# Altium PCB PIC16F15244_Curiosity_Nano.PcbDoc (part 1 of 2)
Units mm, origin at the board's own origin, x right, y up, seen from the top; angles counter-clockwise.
Board outline 50.8 x 20.32 mm, 4 copper layers (Top-Layer, Ground Plane, Power Plane, Bottom Layer), stack 1.59 mm thick; 59 components, 67 nets, 348 pads, 148 vias.
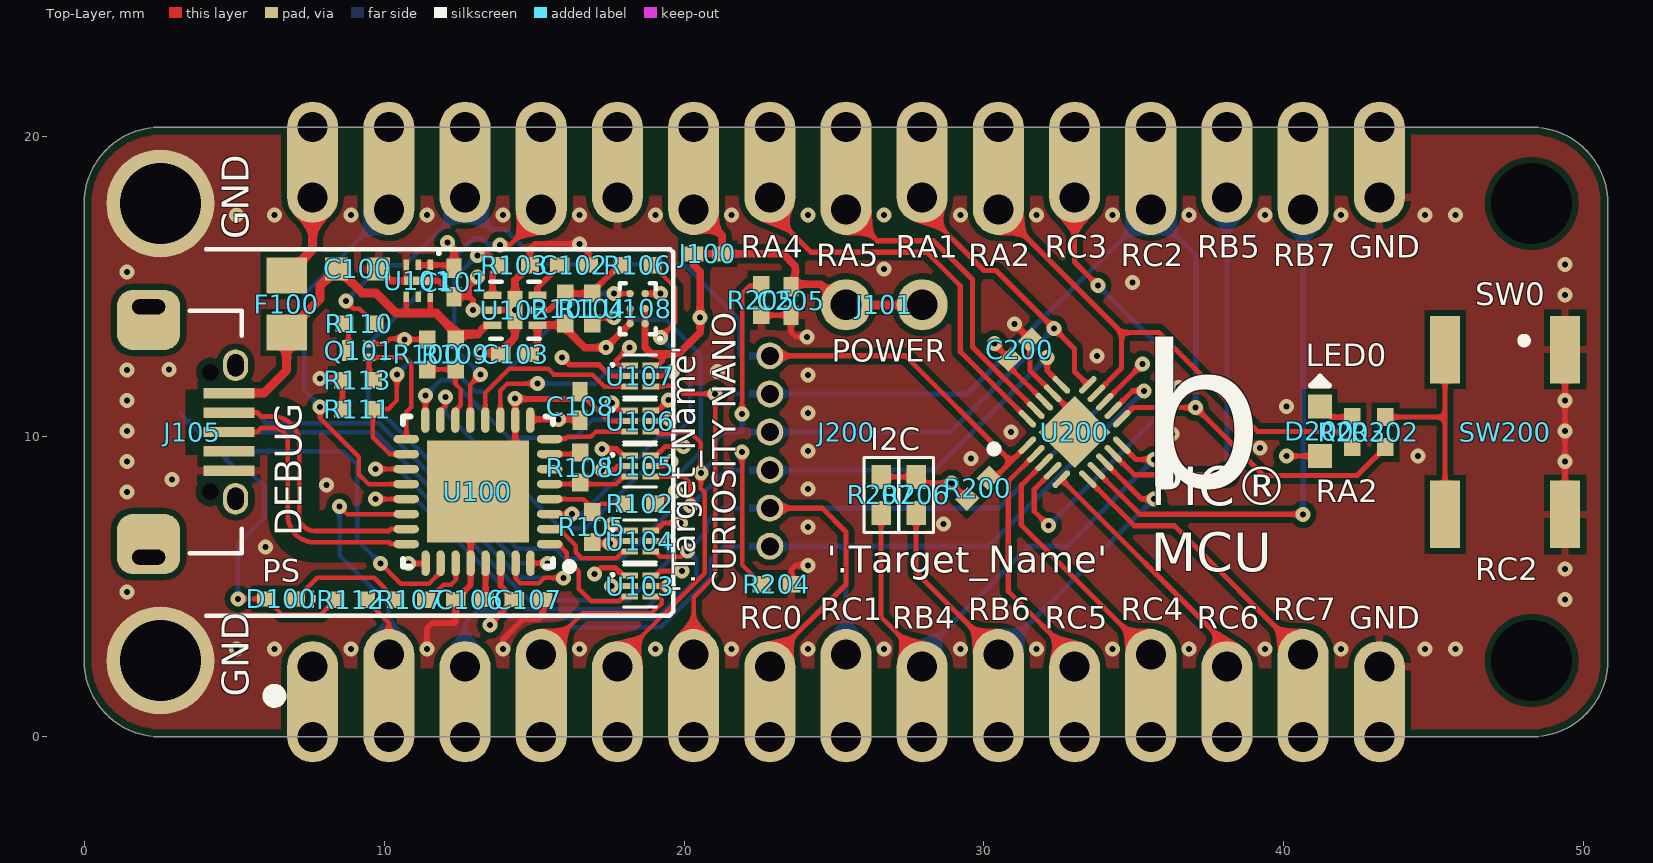
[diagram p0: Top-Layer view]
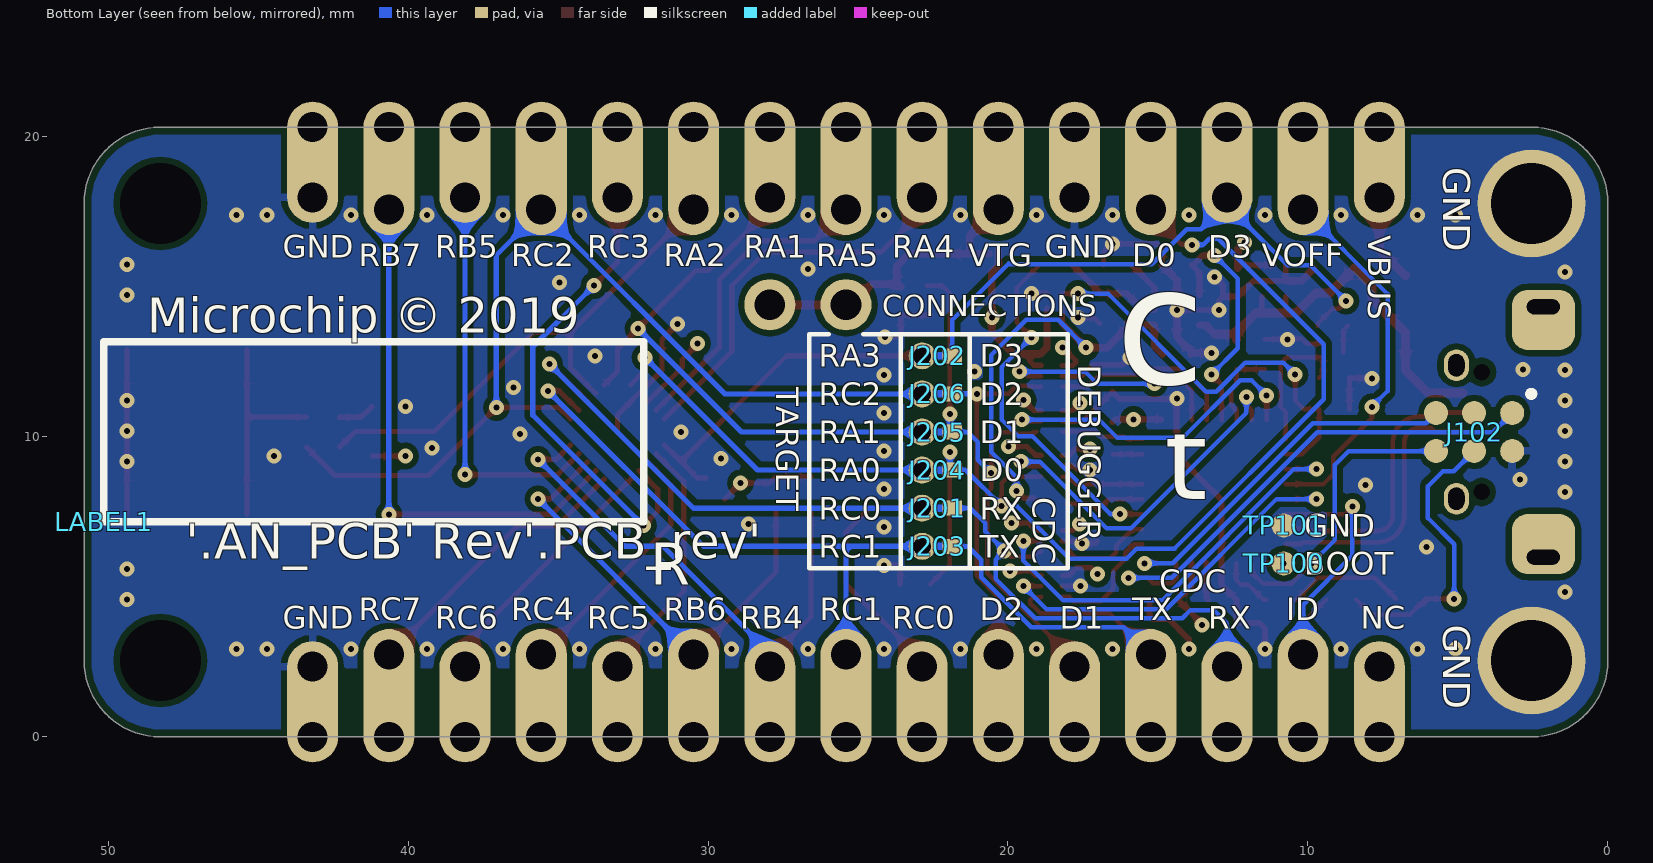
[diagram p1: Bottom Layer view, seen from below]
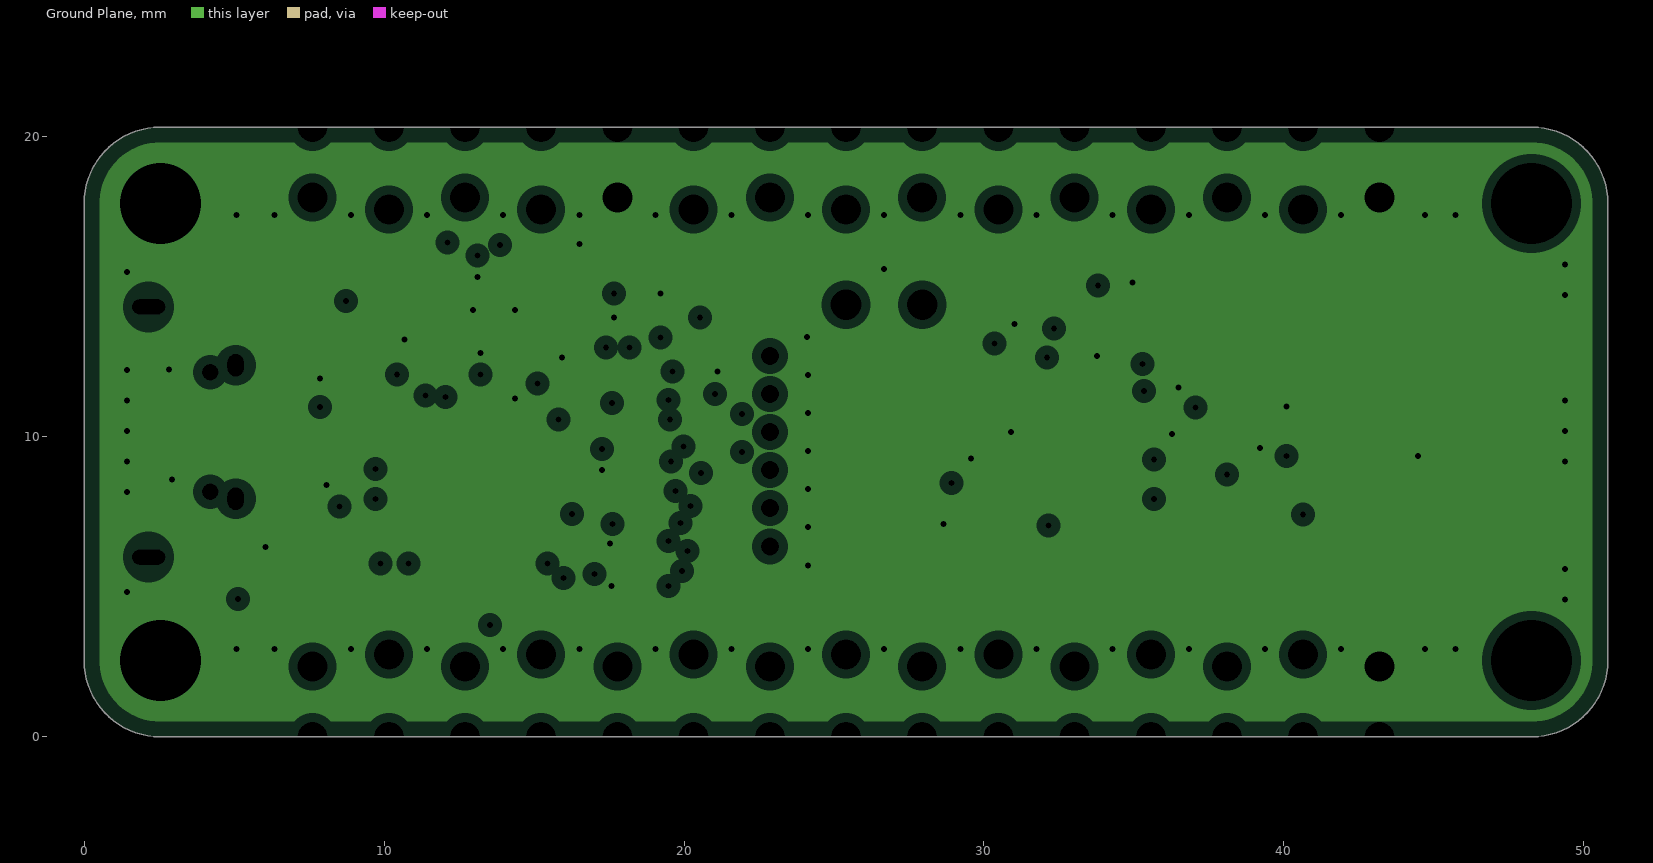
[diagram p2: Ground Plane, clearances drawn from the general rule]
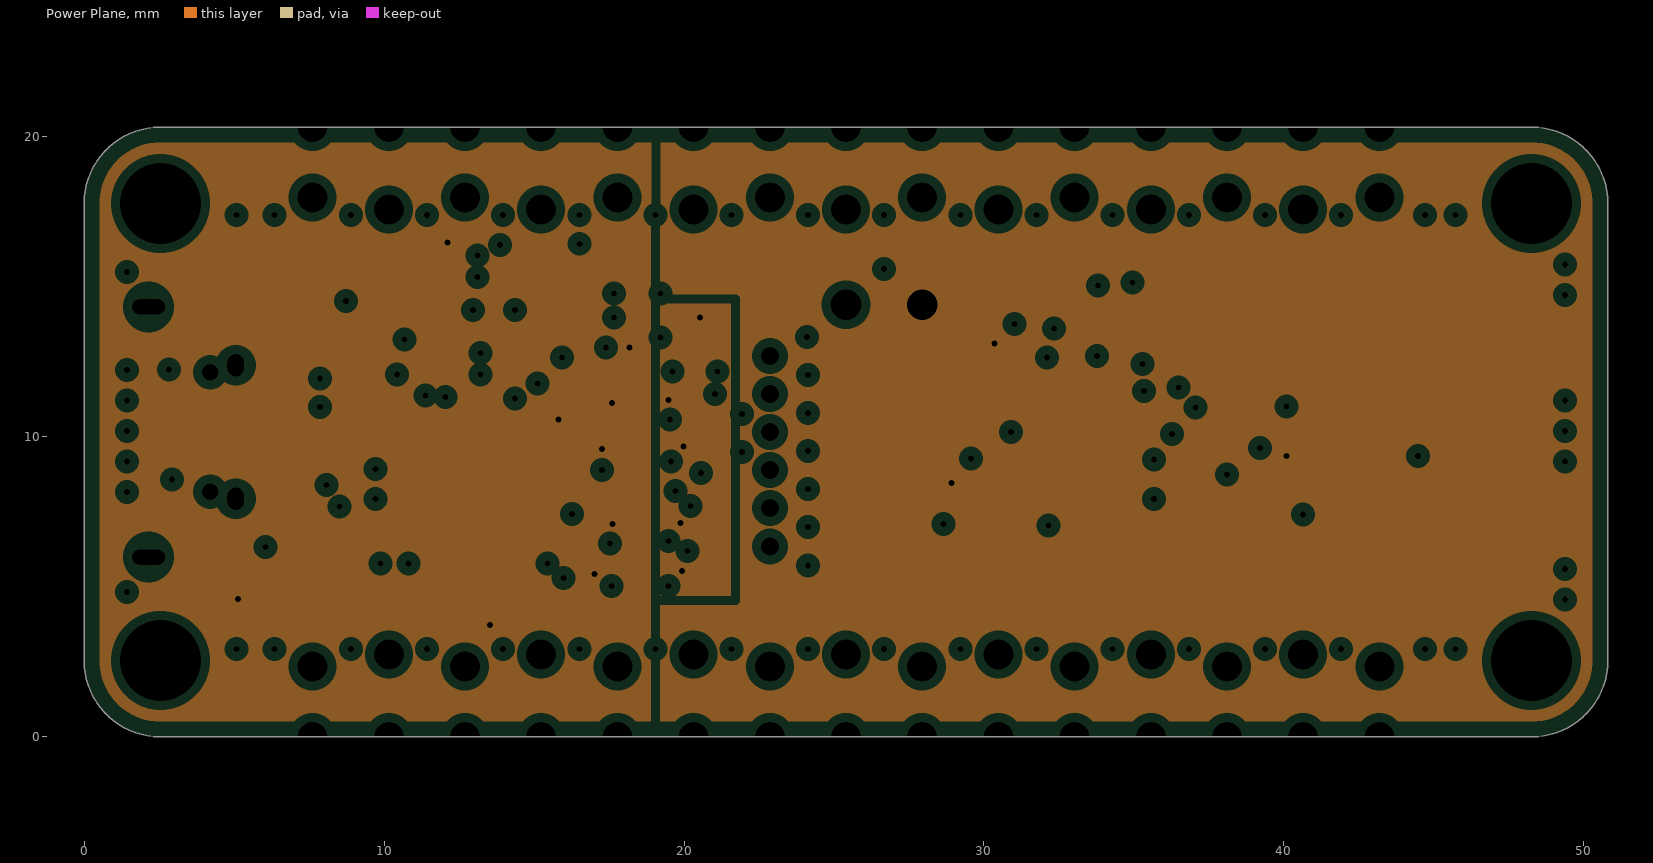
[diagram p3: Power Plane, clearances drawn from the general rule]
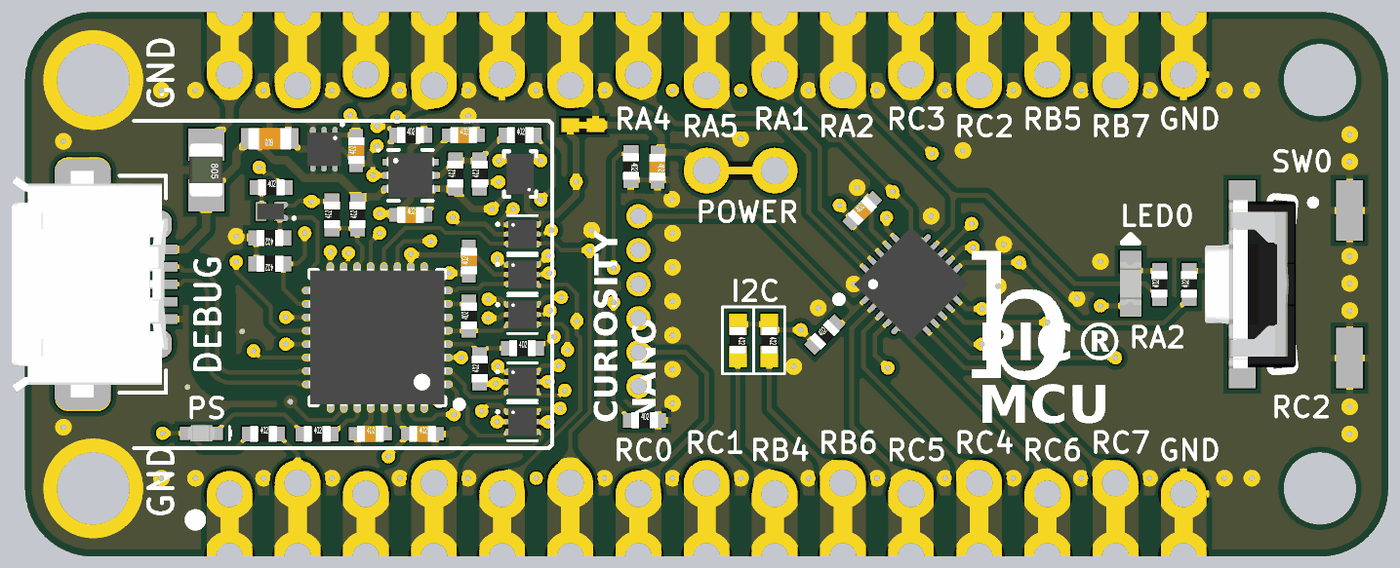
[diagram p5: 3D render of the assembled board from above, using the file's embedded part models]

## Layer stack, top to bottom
Top Solder: solder mask 0.0102, Solder Resist, Dk 3.5
Top-Layer: signal copper 0.035
Dielectric 1: prepreg 0.11, FR-4, Dk 4.2
Ground Plane: plane copper 0.035, net GND
Dielectric 3: core 1.23, Dk 4.2
Power Plane: plane copper 0.035, net (Multiple Nets)
Dielectric 4: prepreg 0.11, Dk 4.2
Bottom Layer: signal copper 0.035
Bottom Solder: solder mask 0.0102, Solder Resist, Dk 3.5

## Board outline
0,2.54 0,17.78 cw(c2.54,17.78) 2.54,20.32 48.26,20.32 cw(c48.26,17.78) 50.8,17.78 50.8,2.54 cw(c48.26,2.54) 48.26,0 2.54,0 cw(c2.54,2.54)

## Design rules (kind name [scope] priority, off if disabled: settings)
AcuteAngle [All] p1: minimum=8.00000000000000E+0001 checktracksonly=TRUE
AssemblyTestPointUsage [All] p1: valid=2 allowmultiple=TRUE
AssemblyTestpoint AssemblyTestpoint_1 [OnBottomLayer and IsComponent] p1: testpointundercomponent=TRUE minsize=0.8 maxsize=2 preferedsize=0.8 minholesize=0 maxholesize=1 preferedholesize=0.25 testpointgrid=0.025 usegrid=FALSE gridtolerance=0 allowsidebottom=TRUE minspacing=1.27 compbodyclearance=1.27
AssemblyTestpoint [All] p2: testpointundercomponent=TRUE minsize=0.8 maxsize=3 preferedsize=0.8 minholesize=0 maxholesize=1 preferedholesize=0.25 testpointgrid=0.025 usegrid=FALSE gridtolerance=0 allowsidebottom=TRUE minspacing=1.27
BoardOutlineClearance BoardOutlineClearance_edge_connector [InComponent('J200') OR InComponent('J201')] p1: gap=0 ignorepadtopadclearanceinfootprint=FALSE
BoardOutlineClearance BoardOutlineClearance_text_top_layer [IsText AND OnTopSilkscreen] p2: gap=0.25 ignorepadtopadclearanceinfootprint=FALSE
BoardOutlineClearance BoardOutlineClearance_FirstPinDot [IsArc AND OnTopSilkscreen] p3: gap=0 ignorepadtopadclearanceinfootprint=FALSE
BoardOutlineClearance [All] p4: gap=0.25 ignorepadtopadclearanceinfootprint=FALSE
Clearance Clearance_Via_in_Pad [IsVia AND (InNet('GND') OR  InNet('BOOT'))] p1: gap=0 ignorepadtopadclearanceinfootprint=FALSE
Clearance Clearance_Poly_Impedance [IsRegion vs InDifferentialPairClass('All Differential Pairs')] p2: gap=0.6 ignorepadtopadclearanceinfootprint=FALSE except(0: Arc-Hole Track-Hole SMDPad-Hole THPad-Hole Via-Hole Fill-Hole Poly-Hole Region-Hole Text-Hole)
Clearance Clearance_Poly [InPoly] p3: gap=0.2 ignorepadtopadclearanceinfootprint=FALSE
Clearance [All] p4: gap=0.15 ignorepadtopadclearanceinfootprint=FALSE
ComponentClearance ComponentClearance_BETWEEN_TESTPOINTS [InComponentClass('Testpoints') vs InComponentClass('Testpoints')] p1: gap=0 collisioncheckmode=3 verticalgap=0 showdistances=FALSE
ComponentClearance ComponentClearance_EDGE [InComponent('J200') or HasFootprint('AP8-01166')] p2: gap=0 collisioncheckmode=3 verticalgap=0 showdistances=FALSE
ComponentClearance ComponentClearance_LABEL [InComponent('LABEL1')] p3: gap=0 collisioncheckmode=3 verticalgap=0 showdistances=FALSE
ComponentClearance [All] p4: gap=0.254 collisioncheckmode=3 verticalgap=0.254 showdistances=TRUE
DiffPairsRouting [All] p1: maxlimit=0.22 minlimit=0.22 mostfreqgap=0.22 toplayer_minwidth=0.16 toplayer_maxwidth=0.16 toplayer_prefwidth=0.16 bottomlayer_minwidth=0.16 bottomlayer_maxwidth=0.16 bottomlayer_prefwidth=0.16 maxuncoupledlength=20
FabricationTestPointUsage TestPointUsage [All] p1: valid=2 allowmultiple=TRUE
FabricationTestpoint Testpoint [All] p1: side=2 testpointundercomponent=TRUE minsize=0.55 maxsize=3 preferedsize=0.8 minholesize=0 maxholesize=1 preferedholesize=0.25 testpointgrid=0 allowsidebottom=TRUE usegrid=FALSE gridtolerance=0 minspacing=1.27
HoleSize [All] p1: absolutevalues=TRUE maxlimit=10 minlimit=0.2 maxpercent=80.000 minpercent=20.000
HoleToHoleClearance HoleToHoleClearance_NPTH [(HoleDiameter > 0) And (PadIsPlated = 'False')] p1: gap=0.25 allowstackedmicrovias=TRUE
HoleToHoleClearance [All] p2: gap=0.3 allowstackedmicrovias=TRUE
MinimumAnnularRing [All] p1: minimumring=0.15
MinimumSolderMaskSliver [All] p1: minsoldermaskwidth=0.08
NetAntennae [Not IsTestpoint] p1: netantennaetolerance=0
PlaneClearance [All] p1: clearance=0.3
PlaneConnect PlaneConnect_VIA [IsVia OR HasPad('Free-666') OR HasPad('Free-EDGE')] p1: planeconnectstyle=Direct reliefexpansion=0.508 reliefentries=4 reliefconductorwidth=0.254 reliefairgap=0.254
PlaneConnect [All] p2: planeconnectstyle=Relief reliefexpansion=0.508 reliefentries=4 reliefconductorwidth=0.254 reliefairgap=0.254
PolygonConnect PolygonConnect_VIA [IsVia OR HasPad('Free-666') OR HasFootprint('AP8-00870')] p1: connectstyle=Direct reliefconductorwidth=0.254 reliefentries=4 polygonreliefangle="90 Angle" airgapwidth=0.254
PolygonConnect [All] p2: connectstyle=Relief reliefconductorwidth=0.254 reliefentries=4 polygonreliefangle="90 Angle" airgapwidth=0.2
RoutingVias [All] p1: holewidth=0.25 width=0.55 viastyle="Through Hole" minholewidth=0.2 minwidth=0.5 maxholewidth=0.5 maxwidth=1
SMDNeckDown [All] p1: percent=98.000
ShortCircuit ShortCircuit_NC_edge_connector [IsPad AND OnLayer('Multi-Layer') AND HasFootprint('AP8-01100') vs IsPad AND OnLayer('Multi-Layer') AND HasFootprint('AP8-01100')] p1: allowed=TRUE
ShortCircuit [All] p2: allowed=FALSE
SilkToSilkClearance SilkToSilkClearance_Text [IsText] p1: silktosilkclearance=0
SilkToSilkClearance [All] p2: silktosilkclearance=0.1
SilkToSolderMaskClearance SilkscreenOverComponentPads_Soldermask [All] p1: minsilkscreentomaskgap=0.12 clearancetoexposedcopper=FALSE
SilkToSolderMaskClearance SilkscreenOverComponentPads_Copper [All] p2: minsilkscreentomaskgap=0.2 clearancetoexposedcopper=TRUE
SolderMaskExpansion SolderMaskTenting [IsVia AND NOT (IsFabTestpoint OR IsAssyTestpoint)] p1: expansion=-1 istentingtop=FALSE
SolderMaskExpansion [All] p2: expansion=0.06 istentingtop=FALSE
ViasUnderSMD ViasUnderSMD_GND [InPadClass('Ground_Pads')] p1: allowed=TRUE
ViasUnderSMD ViasUnderSMD_Testpoint [InNet('BOOT') or InNet('GND')] p2: allowed=TRUE
ViasUnderSMD [All] p3: allowed=FALSE
Width Width_Power [InNetClass('Power')] p1: maxlimit=0.5 minlimit=0.175 preferedwidth=0.25
Width [All] p2: maxlimit=10 minlimit=0.15 preferedwidth=0.15
15 further rules are at their usual default settings.

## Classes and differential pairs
component class S2: C200 C205 D200 J200 J201 J202 J203 J204 J205 J206 R200 R202 R203 R204 R205 R206 R207 SW200 U200
component class S1: C100 C101 C102 C103 C106 C107 C108 D100 F100 J100 J101 J102 J105 Q101 R100 R101 R102 R103 R104 R105 R106 R107 R108 R109 R110 R111 R112 R113 TP100 TP101 U100 U101 U102 U103 U104 U105 U106 U107 U108
component class PIC16F15244_Curiosity_Nano_TopLevel: FW1 LABEL1 PCB1 PCBADOC1 TEST1
differential pair USBD: +USBD_P -USBD_N

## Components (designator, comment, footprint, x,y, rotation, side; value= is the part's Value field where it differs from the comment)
C100 "" AP1-00039 9.118,15.597 r180 top locked value=4.7uF
C101 "Farnell no: 1288200" AP1-00053 12.339,15.15 r90 top locked value=2.2uF
C102 "" AP1-00053 16.34,15.725 r0 top locked value=100n
C103 "" AP1-00053 14.37,12.75 r0 top locked value=2.2uF
C106 "" AP1-00053 12.865,4.575 r0 top locked value=1u
C107 "" AP1-00053 14.815,4.575 r0 top locked value=100n
C108 "" AP1-00053 16.54,11.025 r90 top locked value=100n
C200 "" AP1-00053 31.197,12.909 r45 top value=100n
C205 "" AP1-00053 23.571,14.529 r270 top locked value=2.2uF
D100 "Replacement to A10-0183 / Not proven to be as good at If = 1mA" AP4-00160 6.571,4.6 r180 top locked value="GREEN LED"
D200 "" AP4-00169 41.201,10.181 r270 top locked value="YELLOW LED"
F100 "Farnell no: 1861197" AP2-00002 6.75,14.427 r270 top locked value=MC36213
J100 "" AP8-00595 20.795,16.098 r0 top locked net-tie value="Closed Link"
J101 "" AP8-01183 26.67,14.402 r0 top locked net-tie value="Closed Link 1x2 100mil header"
J102 "" AP8-00997 5.73,10.16 r0 bottom locked value="Testpoint Array"
J105 "" AP8-01099 2.15,10.16 r270 top locked value=MU-MB0142AB2-269
J200 "" AP8-01110 7.62,10.16 r0 top locked value="CNANO30-pin edge connector"
J201 "" AP8-01166 22.335,7.62 r0 bottom locked net-tie value="Closed Link"
J202 "" AP8-01166 22.335,12.7 r0 bottom locked net-tie value="Closed Link"
J203 "" AP8-01166 22.335,6.35 r0 bottom locked net-tie value="Closed Link"
J204 "" AP8-01166 22.335,8.89 r0 bottom locked net-tie value="Closed Link"
J205 "" AP8-01166 22.335,10.16 r0 bottom locked net-tie value="Closed Link"
J206 "" AP8-01166 22.335,11.43 r0 bottom locked net-tie value="Closed Link"
LABEL1 "" AP8-00317 50.14,7.164 r180 bottom value="Label PCBA"
Q101 "" AP5-00056 9.15,12.875 r180 top locked value=DMN65D8LFB
R100 "" AP2-00011 11.439,12.75 r90 top locked value=47k
R101 "" AP2-00011 16.04,14.275 r90 top locked value=47k
R102 "" AP2-00011 18.539,7.775 r0 top locked value=47k
R103 "" AP2-00011 14.365,15.725 r0 top locked value=47k
R104 "" AP2-00011 16.94,14.275 r90 top locked value=27k
R105 "" AP2-00011 16.94,6.999 r90 top locked value=47k
R106 "" AP2-00011 18.452,15.725 r0 top locked value=33k
R107 "" AP2-00011 10.89,4.575 r0 top locked value=1k
R108 "" AP2-00011 16.54,8.974 r90 top locked value=1k
R109 "" AP2-00011 12.389,12.75 r90 top locked value=47k
R110 "" AP2-00011 9.175,13.775 r0 top locked value=1k
R111 "" AP2-00011 9.127,10.922 r180 top value=47k
R112 "" AP2-00011 8.89,4.575 r0 top locked value=1k
R113 "" AP2-00011 9.127,11.887 r180 top value=47k
R200 "" AP2-00011 29.796,8.282 r45 top value=47k
R202 "" AP2-00011 43.385,10.156 r90 top value=1k
R203 "" AP2-00011 42.28,10.156 r90 top value=1k
R204 "" AP2-00011 23.089,5.085 r0 top locked value=47k
R205 "" AP2-00011 22.581,14.554 r270 top locked value=47k
R206 "" AP2-00000 27.737,8.068 r270 top value=4.7k
R207 "" AP2-00000 26.568,8.068 r270 top value=4.7k
SW200 "Rating: DC 12V 50mA / Max 0.1 ohm contact resistance" AP8-00137 47.371,10.16 r270 top locked value=TS604VM1-035CR
TP100 "PCB implemented component." AP8-00870 10.81,5.777 r90 bottom locked value="SMD Test point - 0.8mm"
TP101 "PCB implemented component." AP8-00870 10.81,7.047 r90 bottom locked value="SMD Test point - 0.8mm"
U100 "QFN32" AP6-00418 13.13,8.17 r90 top locked value=SAMD21E18A-MUT
U101 "" AP6-00481 11.139,15.2 r270 top locked value=MIC5528-3.3YMT
U102 "Marking code: AAR" AP6-00504 14.365,14.225 r0 top locked value=MIC5353
U103 "1.05 x 1.05 x 0.4mm" AP6-00505 18.539,5.025 r0 top locked value=74LVC1T45FW4-7
U104 "1.05 x 1.05 x 0.4mm" AP6-00505 18.539,6.525 r0 top locked value=74LVC1T45FW4-7
U105 "1.05 x 1.05 x 0.4mm" AP6-00505 18.539,9.025 r0 top locked value=74LVC1T45FW4-7
U106 "1.05 x 1.05 x 0.4mm" AP6-00505 18.539,10.525 r0 top locked value=74LVC1T45FW4-7
U107 "1.05 x 1.05 x 0.4mm" AP6-00505 18.539,12.025 r0 top locked value=74LVC1T45FW4-7
U108 "" AP6-00513 18.452,14.275 r180 top locked value=MIC94163
U200 "" AP6-00494 33.02,10.16 r45 top value=PIC16F15244-VQFN20

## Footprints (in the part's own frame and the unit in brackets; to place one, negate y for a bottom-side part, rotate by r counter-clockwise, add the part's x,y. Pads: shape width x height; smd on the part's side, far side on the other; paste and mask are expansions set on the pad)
AP1-00039 [mil] "Capacitor 0603 Hight 0.8mm"
  rect 30x30 smd: 1(-27.5,0) 2(27.5,0)
  body extent -31,-16 32,16, height 12
AP1-00053 [mm] "Chip Capacitor, 2-Leads, Body 1.0x0.5mm, IPC High Density"
  rect 0.65x0.5 smd: 1(-0.475,0) 2(0.475,0)
  body extent -0.5,-0.3 0.5,0.3, height 0.2
AP2-00000 [mm] "Standard 0402 SMD resistor footprint"
  rect 0.8x0.65 smd paste-1: 1(-0.6,0) 2(0.6,0)
  silkscreen extent -1.25,-0.58 1.25,0.58, body extent -0.5,-0.3 0.5,0.3, height 0.2
AP2-00002 [mm]
  rect 1.2x1.35 smd: 1(-0.95,0) 2(0.95,0)
  body extent -1,-0.62 1,0.63, height 0.78
AP2-00011 [mm] "Chip Resistor, 2-Leads, Body 1,0x0,5mm, IPC High Density"
  rect 0.6x0.55 smd: 1(-0.5,0) 2(0.5,0)
  body extent -0.5,-0.3 0.5,0.3, height 0.2
AP4-00160 [mm] "ROHM SML-P11 0402 LED"
  rect 0.6x0.5 smd: 1(-0.5,0) 2(0.5,0)
  silkscreen extent -1.14,-0.25 -1.05,0.25, body extent -0.5,-0.3 0.5,0.3, height 0.19
AP4-00169 [mm] "ROHM SML-D1x 0603 LED"
  rect 0.8x0.8 smd: 1(-0.825,0) 2(0.825,0)
  silkscreen extent -1.83,-0.3 -1.53,0.3, body extent -0.8,-0.4 0.8,0.4, height 0.54
AP5-00056 [mm] "DFN1006-3/SOT883, 3-Leads, Body 1,050x0,65mm, Pitch 0,35mm"
  oval 0.508x0.229 on Top Paste: 0(-0.4,0.25) 0(-0.4,-0.25)
  rect 0.4x0.25 smd paste-1: 1(-0.35,0.225) 2(-0.35,-0.225)
  rect 0.4x0.7 smd: 3(0.35,0)
  silkscreen extent -0.92,0.2 -0.83,0.3, body extent -0.5,-0.3 0.5,0.3, height 0.49
AP6-00418 [mm] "MLF-32 solder foot print"
  oval 0.28x0.85 smd paste-0.03 mask+0: 1(-1.746,-2.39) 2(-1.246,-2.39) 3(-0.746,-2.39) 4(-0.246,-2.39) 5(0.254,-2.39) 6(0.754,-2.39) 7(1.254,-2.39) 8(1.754,-2.39) 17(1.754,2.39) 18(1.254,2.39) 19(0.754,2.39) 20(0.254,2.39) 21(-0.246,2.39) 22(-0.746,2.39) 23(-1.246,2.39) 24(-1.746,2.39)
  oval 0.85x0.28 smd paste-0.03 mask+0: 9(2.386,-1.746) 10(2.386,-1.246) 11(2.386,-0.746) 12(2.386,-0.246) 13(2.386,0.254) 14(2.386,0.754) 15(2.386,1.254) 16(2.386,1.754) 25(-2.383,1.746) 26(-2.383,1.246) 27(-2.383,0.746) 28(-2.383,0.246) 29(-2.383,-0.254) 30(-2.383,-0.754) 31(-2.383,-1.254) 32(-2.386,-1.75)
  rect 3.4x3.4 smd paste-1.7 mask+0: 33(0.004,0)
  silkscreen extent -2.62,-3.18 2.5,2.5, body extent -2.55,-2.55 2.55,2.55, height 1
AP6-00481 [mm] "6 Pin 1.2mm X 1.2mm Thin DFN"
  oval 0.483x0.203 on Top Paste: 0(-0.597,0.412) 0(-0.597,0) 0(-0.597,-0.412) 0(0.597,0.412) 0(0.597,0) 0(0.597,-0.412)
  rect 0.35x0.18 smd paste-0.09 mask+0.05: 1(-0.531,0.4) 2(-0.531,0) 3(-0.531,-0.4) 4(0.531,-0.4) 5(0.531,0) 6(0.531,0.4)
  rect 0.28x0.94 smd paste-0.02 mask+0.05: 7(0,0)
  silkscreen extent -0.97,0.64 -0.88,0.74, body extent -0.63,-0.62 0.63,0.63, height 0.6
AP6-00494 [mm] "20-pad, 3 x 3 x 0.85 mm body, lead pin pitch 0.4mm. Plastic Very Thin Quad Flat No Lead Package (VQFN) Sawn"
  oval 0.75x0.2 smd mask+0.06: 1(-1.425,0.8) 2(-1.425,0.4) 3(-1.425,0) 4(-1.425,-0.4) 5(-1.425,-0.8) 11(1.425,-0.8) 12(1.425,-0.4) 13(1.425,0) 14(1.425,0.4) 15(1.425,0.8)
  oval 0.2x0.75 smd mask+0.06: 6(-0.8,-1.425) 7(-0.4,-1.425) 8(0,-1.425) 9(0.4,-1.425) 10(0.8,-1.425) 16(0.8,1.425) 17(0.4,1.425) 18(0,1.425) 19(-0.4,1.425) 20(-0.8,1.425)
  rect 1.7x1.7 smd paste-2 mask+0.06: 21(0,0)
  silkscreen extent -2.42,1.38 -2.18,1.62, body extent -1.5,-1.5 1.5,1.5, height 0.9
AP6-00504 [mm] "MLF, 6-Leads, Body 1,60x1,60mm, Pitch 0,50mm, Thermal Pad 1,26x0,33mm, IPC High Density"
  rect 0.6x0.25 smd mask+0.05: 1(-0.75,0.5) 2(-0.75,0) 3(-0.75,-0.5) 4(0.75,-0.5) 5(0.75,0) 6(0.75,0.5)
  rect 0.5x1.26 smd paste-0.1 mask+0.05: 7(0,0)
  silkscreen extent -1.25,-0.95 0.82,1, body extent -0.87,-0.82 0.87,0.82, height 0.55
AP6-00505 [mm] "X2-DFN1010, 6-Leads, Body 1,05x1,05mm, Pitch 0,35mm, IPC High Density"
  oval 0.559x0.178 on Top Paste: 0(-0.375,-0.401) 0(-0.375,0) 0(-0.375,0.401) 0(0.375,-0.401) 0(0.375,0) 0(0.375,0.401)
  rect 0.55x0.2 smd paste-0.1: 1(-0.35,0.35) 2(-0.35,0) 3(-0.35,-0.35) 4(0.35,-0.35) 5(0.35,0) 6(0.35,0.35)
  silkscreen extent -0.97,-0.7 0.55,0.7, body extent -0.53,-0.53 0.53,0.53, height 0.4
AP6-00513 [mm] "BGA, 6-Leads, Body 1,00x1,50mmx0,80mm, Pitch 0,50mm"
  round 0.25 smd mask+0.05: A1(-0.25,0.5) A2(0.25,0.5) B1(-0.25,0) B2(0.25,0) C1(-0.25,-0.5) C2(0.25,-0.5)
  silkscreen extent -0.8,-0.85 0.6,1.05, body extent -0.5,-0.75 0.5,0.75, height 0.8
AP8-00137 [mm]
  rect 2.25x1 smd: 1(-2.75,2) 2(2.75,2) 3(-2.75,-2) 4(2.75,-2)
  silkscreen extent -3.15,0.54 -2.95,0.73, body extent -3.4,-3.21 3.4,3.22, height 3.47
AP8-00317 [mm] "Placement area for 18x6mm sticker"
  silkscreen extent 0,0 18,6
AP8-00595 [mm]
  rect 0.65x0.5 smd paste-1: 1(-0.475,0) 2(0.475,0)
  Top-Layer lines w0.254: -0.175,0 0.2,0
AP8-00870 [mil] "TP_SMT_.8mm"
  round 31.5 smd paste-39.37: 1(0,0)
AP8-00997 [mm] "SMT test point array 2x5 0.8mm, Pitch 1.27 mm"
  round 0.8 smd paste-1: 1(-2.54,-0.635) 2(-2.54,0.635) 3(-1.27,-0.635) 4(-1.27,0.635) 5(0,-0.635) 6(0,0.635)
  silkscreen extent -3.28,-1.37 -3.07,-1.17
AP8-01099 [mm] "Micro USB AB connector from Allen Creations. Signals surface mount, shield DIP"
  rrect52% 2x2.1 on Top Paste: 0(-3.69,0) 0(3.69,0)
  rrect100% 1.05x0.84 on Top Paste: 0(-2.225,2.9) 0(2.225,2.9)
  rect 0.35x1.7 smd: 1(-1.3,2.68) 2(-0.65,2.68) 3(0,2.68) 4(0.65,2.68) 5(1.3,2.68)
  rrect52% 2x2.1 hole 0.5 slot 1.1 at 90 deg copper offset 0.437,0: 6(-4.175,0)
  rrect52% 2x2.1 hole 0.5 slot 1.1 at 90 deg copper offset -0.437,0: 7(4.175,0)
  rrect100% 1.05x0.84 hole 0.54 slot 0.75 at 0 deg: 8(-2.225,2.9) 9(2.225,2.9)
  round 0 hole 0.55 unplated: 10(-2,2.05) 11(2,2.05)
  silkscreen extent -4.05,1.38 4.05,3.1, body extent -4.32,-2.65 4.33,3.25, height 2.78
AP8-01110 [mil] "30-pin Header staggered with castellations (for CNANO)"
  round 75 on Top Solder: 0(0,-400) 0(0,400) 0(100,-400) 0(100,400) 0(200,-400) 0(200,400) 0(300,-400) 0(300,400) 0(400,-400) 0(400,400) 0(500,-400) 0(500,400) 0(600,-400) 0(600,400) 0(700,-400) 0(700,400) 0(800,-400) 0(800,400) 0(900,-400) 0(900,400) 0(1000,-400) 0(1000,400) 0(1100,-400) 0(1100,400) 0(1200,-400) 0(1200,400) 0(1300,-400) 0(1300,400) 0(1400,-400) 0(1400,400)
  oval 67x155 hole 39.37 copper offset 0,44 mask-20: 1(0,-400) 3(200,-400) 5(400,-400) 7(600,-400) 9(800,-400) 11(1000,-400) 13(1200,-400) 15(1400,-400)
  round 67 hole 39.37 mask+3.94: 1(0,-308) 2(100,-292) 3(200,-308) 4(300,-292) 5(400,-308) 6(500,-292) 7(600,-308) 8(700,-292) 9(800,-308) 10(900,-292) 11(1000,-308) 12(1100,-292) 13(1200,-308) 14(1300,-292) 15(1400,-308) 16(1400,308) 17(1300,292) 18(1200,308) 19(1100,292) 20(1000,308) 21(900,292) 22(800,308) 23(700,292) 24(600,308) 25(500,292) 26(400,308) 27(300,292) 28(200,308) 29(100,292) 30(0,308)
  oval 67x171 hole 39.37 copper offset 0,52 mask-20: 2(100,-400) 4(300,-400) 6(500,-400) 8(700,-400) 10(900,-400) 12(1100,-400) 14(1300,-400)
  oval 67x155 hole 39.37 copper offset 0,-44 mask-20: 16(1400,400) 18(1200,400) 20(1000,400) 22(800,400) 24(600,400) 26(400,400) 28(200,400) 30(0,400)
  oval 67x171 hole 39.37 copper offset 0,-52 mask-20: 17(1300,400) 19(1100,400) 21(900,400) 23(700,400) 25(500,400) 27(300,400) 29(100,400)
  Multi-Layer pour cut-out: 1434,310 1434,450 -34,450 -34,310
  Multi-Layer pour cut-out: -34,-310 -34,-450 1434,-450 1434,-310
AP8-01166 [mm] "Cut-Strap 0402 with hole"
  rect 0.65x0.5 smd paste-1: 1(-0.475,0)
  round 0.9 hole 0.6 paste-1: 2(0.525,0)
  Top-Layer region: -0.175,0.125 0.175,0.125 0.175,-0.125 -0.175,-0.125
AP8-01183 [mm] "closed link, 100-mil 1 x 2 pin header footprint"
  round 1.7 hole 1.02: 1(-1.27,0) 2(1.27,0)
  Top-Layer lines w0.3: -1.27,0 1.27,0

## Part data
C100: library part A01-0377, "Ceramic capacitor, SMD 0603, X5R, 10V, 10% (de31036)", Manufacturer="WALSIN Technology Corporation", MPN=0603X475K100CT, TemperatureRange="-55 - +85 deg C", Tolerance=10%
C101: library part A01-0300, "Ceramic capacitor, SMD 0402, X5R, 6.3V, +/-20%", Manufacturer=Kemet, MPN=C0402C225M9PAC, TemperatureRange="-55Â°C to +85Â°C", Tolerance=Â±20%
C102 C107 C108 C200: library part A01-0246, "Ceramic capacitor, SMD 0402, X7R, 16V, +/-10%", Manufacturer=Kemet, MPN=C0402C104K4RACTU, TemperatureRange="-55 - +125 deg C", Tolerance="16V, +/-10%"
C103 C205: library part A01-0493, "CAP CER 2.2UF 10V 10% X5R 0402", Manufacturer=tdk, MPN=C1005X5R1A225K, TemperatureRange="-55 to 85C", Tolerance=+/-10%
C106: library part A01-0286, "Ceramic capacitor, SMD 0402, X5R, 6.3V, +/-10% (de26942)", Manufacturer=Kemet, MPN=C0402C105K9PAC, TemperatureRange="-55 to 85 deg C", Tolerance=+/-10%
D100: library part A10-0213, "LED, SMD 0402, Green, Wave length=569nm, 2.1mcd @ (1mA, 1.9Vf)rohm", Manufacturer=ROHM, MPN=SML-P12MTT86R, TemperatureRange="-40 to +85"
D200: library part A10-0218, "LED, SMD 0603, Yellow, Wave length=590nm, 100mcd @ (20mA, 2.2Vf) rohm", Manufacturer=ROHM, MPN=SML-D12Y1WT86, TemperatureRange="-40 to +85"
F100: library part A02-0622, "Resetable PTC fuse, Ih = 0.5A, It = 1.0A, 0805 package", Manufacturer=Multicomp, MPN=MC36213, TemperatureRange="-40°C to + 85°C"
J100: library part A08-1454, "Closed Link 0402"
J101: library part A08-3029, "Closed Link with w/hole for 1x2 100mil header"
J102: library part A08-2568, "10-pin Testpoint Array, 0.8mm Pad, 1.27mm Pitch"
J105: library part A08-2839, "USB micro AB, Surface mount signals and DIP shield", Manufacturer="Allen Creations Corp.", MPN=MU-MB0142AB2-269, TemperatureRange="-30Â°C to +80Â°C"
J200: library part A08-2846, "Curiosity Nano 30-pin edge connector with castellations, 100-mil pitch."
J201 J202 J203 J204 J205 J206: library part A08-2981, "Closed Link 0402 w/50mil hole"
LABEL1: library part A09-0611, "PCBA identification label PP Top White Gloss", Manufacturer="ACT Logimark AS", MPN=505462
Q101: library part A05-0180, "N-channel MOSFET, DFN1006-3 (SOT883), 60V, 330mA, 4Ohm", Manufacturer="Diodes Incorporated", MPN=DMN65D8LFB-7, TemperatureRange="-55Â°C to +150Â°C"
R100 R101 R102 R103 R105 R109 R111 R113 R200 R204 R205: library part A02-0252, "Thick film resistor, SMD 0402, 1/16W, 1%", Manufacturer=KOA, MPN=RK73H1ETTP4702F, TemperatureRange="-55 - +125 deg C", Tolerance="1 %"
R104: library part A02-0246, "Thick film resistor, SMD 0402, 1/16W, 1%", Manufacturer=Yageo, MPN=RC0402FR-0727KL, TemperatureRange="-55 - +125 deg C", Tolerance="1 %"
R106: library part A02-0248, "Thick film resistor, SMD 0402, 1/16W, 1%", Manufacturer="ASJ Holdings", MPN=CR10-3302-FK, TemperatureRange="-55 - +125 deg C", Tolerance="1 %"
R107 R108 R110 R112 R202 R203: library part A02-0212, "Thick film resistor, SMD 0402, 1/16W, 1%", Manufacturer="ASJ Holdings", MPN=CR10-1001-FK, TemperatureRange="-55 - +125 deg C", Tolerance="1 %"
R206 R207: library part A02-1016, "Thick film resistror, SMD 0402, 1/16W, 1%", Manufacturer=Yageo, MPN=RC0402FR-074K7L, TemperatureRange="-55 to +155 deg C", Tolerance=1%
SW200: library part A08-2830, "SWITCH, SMD, 260gf, 6.4mm X 6.2mm", Manufacturer="Dailywell Electronics Co.LTD", MPN=TS604VM1-035CR-R, TemperatureRange="-40 - +85 deg C"
TP100 TP101: library part A08-2176, "SMD Test point - 0.8mm"
U100: library part A06-1205, "32-bit RISC MCU 32pin", Manufacturer=Microchip, MPN=ATSAMD21E18A-MUT, TemperatureRange="-40Â°C to +85Â°C"
U101: library part A06-1475, "LDO 3.3V 0.5A 6TDFN", Manufacturer=Microchip, MPN=MIC5528-3.3YMT-T5, TemperatureRange="-40Â°C ~ 125Â°C"
U102: library part A06-1578, "500mA Ultra Low Dropout LDO regulator, 2% accuracy, 1.6x1.6mm MLF", Manufacturer=Microchip, MPN=MIC5353YMT-TR, TemperatureRange="-40Â°C to +125Â°C"
U103 U104 U105 U106 U107: library part A06-1580, "Single-Bit Dual-Supply Transceive, 1.65-5.5 Translation and 3-State Outputs", Manufacturer="Diodes Incorporated", MPN=74LVC1T45FW4-7, TemperatureRange="-40C - 125C"
U108: library part A06-1613, "Loadswitch, Rds(on) = 14.5mohm, 1.0mm x 1.5mm WLCSP, reverse blocking", Manufacturer=Microchip, MPN=MIC94163YCS-TR, TemperatureRange="-40Â°C to +125Â°C"
U200: library part A06-1719, "PIC 8-bit RISC MCU, VQFN-20, 3mm x 3mm", Manufacturer=Microchip, MPN=PIC16F15244-I/REB, TemperatureRange="-40°C to 85°C"

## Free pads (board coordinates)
  round 0 hole 2.7 unplated paste-2.6: 0(48.26,2.54) 0(48.26,17.78)
  round 3.6 hole 2.7 paste-2.6: 666(2.54,2.54) 666(2.54,17.78)

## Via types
v1: diameter 0.5, hole 0.2, Top-Layer to Bottom Layer, 144 vias
v2: diameter 0.5, hole 0.2, Top-Layer to Bottom Layer, tented both sides, 2 vias
v3: diameter 0.5, hole 0.2, Top-Layer to Bottom Layer, tented top, 2 vias

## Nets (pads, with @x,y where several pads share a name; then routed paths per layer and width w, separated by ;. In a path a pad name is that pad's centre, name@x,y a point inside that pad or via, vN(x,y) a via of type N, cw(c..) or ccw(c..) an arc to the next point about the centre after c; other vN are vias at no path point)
BOOT: TP100.1 U100.25 | length 0.6
  Top-Layer w0.2: v3(10.81,5.777) U100.25@11.393,5.777
CDC_RX: J200.3 J201.1 U104.4 | length 14.8
  Top-Layer w0.15: U104.4@18.889,6.175 19.031,6.175 19.206,6 19.915,6 v1(20.115,6.2)
  Bottom Layer w0.15: J200.3@12.7,2.54 12.7,3.785 13.14,4.225 13.915,4.225 14.19,3.95 19.096,3.95 20.415,5.269 20.415,5.9 v1(20.115,6.2) 20.752,6.837 20.752,7.117 21.255,7.62 J201.1@21.86,7.62 ; J201.1@21.86,7.61 J201.1@21.91,7.61
CDC_RX_CTRL: U100.19 U104.5 | length 14.4
  Top-Layer w0.15: v1(9.715,8.925) U100.19@10.74,8.924 ; U104.5@18.889,6.525 v1(19.49,6.525)
  Bottom Layer w0.15: v1(9.715,8.925) 10.47,8.925 14.845,4.55 18.165,4.55 19.49,5.875 v1(19.49,6.525)
CDC_TX: J200.4 J203.1 U103.4 | length 13.7
  Top-Layer w0.15: J200.4@15.24,2.743 16.622,4.125 18.925,4.125 19.15,4.35 19.165,4.35 19.253,4.438 19.253,4.562 19.165,4.65 18.914,4.65 U103.4@18.889,4.675
  Bottom Layer w0.15: J200.4@15.24,2.743 16.147,3.65 19.22,3.65 20.89,5.32 20.89,5.9 21.34,6.35 J203.1@21.86,6.35
CDC_TX_CTRL: U100.21 U103.5 | length 13.2
  Top-Layer w0.15: v1(9.715,7.924) U100.21@10.74,7.924 ; U103.5@18.889,5.025 v1(19.49,5.025)
  Bottom Layer w0.15: v1@9.715,7.925 11.046,7.925 14.721,4.25 18.715,4.25 v1(19.49,5.025)
DAC: R106.2 U100.3 | length 12.1
  Top-Layer w0.15: U100.3@15.52,7.424 v1(16.264,7.424) ; R106.2@18.952,15.725 19.714,14.963 19.714,13.816 v1(19.215,13.317) v1@19.215,13.267
  Bottom Layer w0.15: v1(16.264,7.424) 16.589,7.424 19.189,10.024 19.664,10.024 20.215,10.575 20.215,12.317 v1(19.215,13.317)
DBG0: J200.27 J204.1 R204.1 U105.4 | length 33
  Top-Layer w0.15: v1(13.865,16.4) 13.881,16.416 14.221,16.416 15.24,17.435 J200.27@15.24,17.577 ; U105.4@18.889,8.675 19.987,8.675 20.215,8.447 v1(20.215,7.7) ; v1(21.935,9.485) 21.935,5.739 R204.1@22.589,5.085
  Bottom Layer w0.15: v1(13.865,16.4) 13.49,16.4 13.29,16.6 12.987,16.6 9.473,13.086 9.473,11.248 14.446,6.275 15.71,6.275 16.044,5.941 17.956,5.941 19.715,7.7 v1(20.215,7.7) 21.405,8.89 J204.1@21.86,8.89 ; J204.1@21.935,8.89 v1(21.935,9.485)
DBG0_CTRL: U100.15 U105.5 | length 12.1
  Top-Layer w0.15: U100.15@11.876,10.556 11.876,10.861 12.051,11.036 v1(12.051,11.325) ; U105.5@18.889,9.025 19.332,9.025 19.482,9.175 v1(19.564,9.175)
  Bottom Layer w0.15: v1(12.051,11.325) 12.051,10.796 15.903,6.944 16.713,6.944 18.943,9.175 v1(19.564,9.175)
DBG1: J200.5 J205.1 R205.1 U106.4 | length 17.9
  Top-Layer w0.15: J200.5@17.78,2.54 20.69,5.45 20.69,8.15 20.565,8.275 v1(20.565,8.79) 20.565,9.794 20.209,10.15 19.786,10.15 19.736,10.1 19.14,10.1 U106.4@19.065,10.175 ; v1(21.935,10.755) 21.935,13.325 21.935,14.785 22.186,15.036 R205.1@22.703,15.036
  Bottom Layer w0.15: v1(20.565,8.79) 21.008,9.233 21.008,9.825 21.343,10.16 J205.1@21.86,10.16 ; J205.1@21.935,10.16 v1(21.935,10.755)
DBG1_CTRL: U100.16 U106.5 | length 10.9
  Top-Layer w0.15: U100.16@11.376,10.556 v1(11.376,11.375) ; U106.5@18.889,10.525 v1@19.514,10.525
  Bottom Layer w0.15: v1(11.376,11.375) 11.881,11.88 12.26,11.88 14.165,9.975 16.365,9.975 16.965,10.575 v1(19.539,10.575)
DBG2: J200.6 J206.1 U107.4 | length 12.3
  Top-Layer w0.15: U107.4@18.889,11.675 19.315,11.675 19.34,11.7 19.715,11.7 19.98,11.435 v1@21.015,11.435 ; J200.6@20.32,2.54 20.32,4.656 21.04,5.376 v1(21.04,11.435)
  Bottom Layer w0.15: v1@21.015,11.435 v1(21.04,11.435) J206.1@21.86,11.435
DBG2_CTRL: U100.11 U107.5 | length 8
  Top-Layer w0.15: U100.11@13.876,10.556 13.876,11.537 14.114,11.775 v1(15.115,11.775) ; U107.5@18.889,12.025 19.34,12.025 19.49,12.175 v1(19.614,12.175) v1@19.714,12.175
  Bottom Layer w0.15: v1(15.115,11.775) 17.031,11.775 17.431,12.175 v1(19.614,12.175) v1@19.714,12.175
DBG2_GPIO: U100.12 U107.3 | length 6.3
  Top-Layer w0.15: U100.12@13.376,10.556 13.376,11.461 14.182,12.267 15.473,12.267 15.665,12.075 16.939,12.075 17.339,11.675 U107.3@18.189,11.675
DBG3: J200.28 J202.1 R110.2 | length 18.6
  Top-Layer w0.15: v1(8.725,14.525) 8.975,14.275 9.175,14.275 R110.2@9.674,13.776 ; R110.2@9.674,13.7 R110.2@9.674,13.776 ; R110.2@9.675,13.775 R110.2@9.674,13.776
  Bottom Layer w0.15: v1(8.725,14.525) 9.925,15.725 10.693,15.725 11.918,16.95 11.925,16.95 12.7,17.725 12.7,17.78 13.555,16.925 13.772,16.925 13.773,16.924 14.041,16.924 15.212,15.753 19.977,15.753 ; 19.977,15.778 21.86,13.895 ; J202.1@21.86,12.7 21.86,13.87
DBG3_CTRL: Q101.1 R113.1 U100.17 | length 4.8
  Top-Layer w0.15: R113.1@9.619,11.963 9.5,12.082 Q101.1@9.5,12.65 10.702,12.65 10.901,12.451 10.901,10.986 10.74,10.825 U100.17@10.74,9.924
